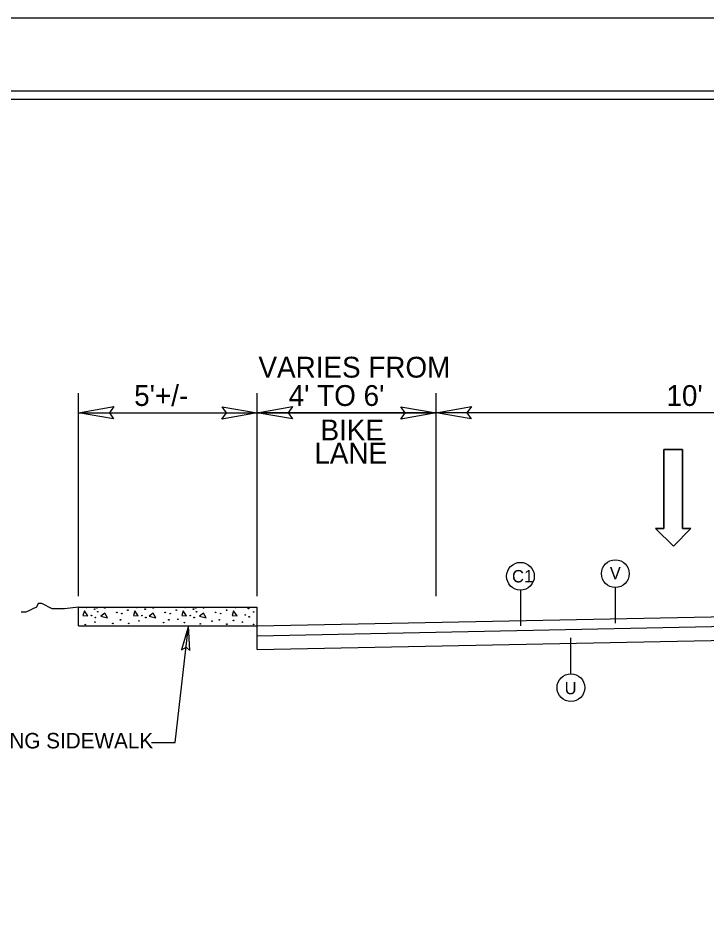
# Model space of a CAD drawing. Extents: x 1022283 to 1026986, y 174822 to 180471.
# Drawn here: x 1023136 to 1023665, y 179772 to 180471 of the extents above; entities that cross this region are included whole.
import ezdxf

# ---------------------------------------------------------------- set-up
doc = ezdxf.new("R2010")
doc.units = 0
for name, color, linetype in [('Default', 7, 'Continuous'), ('Old_Level_9', 7, 'Continuous'), ('Prop Dimension', 7, 'Continuous'), ('Prop Lane Arrow CELL', 7, 'Continuous'), ('Prop Terminator CELL', 7, 'Continuous'), ('Sheet Cutting Line CELL', 7, 'Continuous'), ('Sheet Plot Border Inside CELL', 7, 'Continuous'), ('Sheet Plot Border Outside CELL', 7, 'Continuous'), ('Sheet Typical CELL', 7, 'Continuous'), ('Typical Curb CELL', 7, 'Continuous'), ('Typical ID Circle CELL', 7, 'Continuous'), ('Typical Slope Point Local CELL', 7, 'Continuous'), ('Typical Text General CELL', 7, 'Continuous'), ('Typical Text ID Circle CELL', 7, 'Continuous')]:
    doc.layers.add(name, color=color, linetype=linetype)

# ---------------------------------------------------------------- blocks, each defined once
blk = doc.blocks.new('Lane Arrow Through')
at = {"layer": 'Prop Lane Arrow CELL'}
for p, q in [((-3.15, 1.6), (-3.15, 3.1)), ((-3.15, 3.1), (0, 0)), ((-17.15, 1.6), (-3.15, 1.6)), ((-17.15, -1.7), (-17.15, 1.6)), ((0, 0), (-3.15, -3.2)), ((-3.15, -1.7), (-17.15, -1.7)), ((-3.15, -3.2), (-3.15, -1.7))]:
    blk.add_line(p, q, dxfattribs=at)
blk = doc.blocks.new('Terminator')
at = {"layer": 'Prop Terminator CELL'}
blk.add_lwpolyline([(-9, 1.55), (0, 0), (-9.05, -1.6), (-7.9, 0)], close=True, dxfattribs=at)

msp = doc.modelspace()

# ---------------------------------------------------------------- linework, layer by layer
at = {"layer": 'Default'}
for p, q in [((1023182.77, 180027.22), (1023182.77, 180183.23)), ((1023182.77, 180027.22), (1023182.77, 180183.23)), ((1023182.77, 180027.22), (1023182.77, 180183.23)), ((1023320.14, 180027.22), (1023320.14, 180183.23)), ((1023320.14, 180027.22), (1023320.14, 180183.23)), ((1023457.52, 180027.22), (1023457.52, 180183.23)), ((1023182.77, 180168.23), (1023320.14, 180168.23)), ((1023182.77, 180168.23), (1023320.14, 180168.23)), ((1023827.85, 180168.23), (1023320.14, 180168.23)), ((1023827.85, 180168.23), (1023320.14, 180168.23)), ((1023320.14, 180168.23), (1023457.52, 180168.23))]:
    msp.add_line(p, q, dxfattribs=at)
at = {"layer": 'Old_Level_9'}
msp.add_lwpolyline([(1023639.83, 180065.79), (1023653.25, 180079.43), (1023646.76, 180079.43), (1023646.76, 180140.04), (1023632.47, 180140.04), (1023632.47, 180079.43), (1023625.97, 180079.43)], close=True, dxfattribs=at)
at = {"layer": 'Prop Dimension'}
for p, q in [((1023320.14, 180004.43), (1023827.85, 180014.58)), ((1023320.14, 180004.43), (1023827.85, 180014.58)), ((1023256.91, 179914.73), (1023267.27, 180004.43)), ((1023320.14, 179996.92), (1023827.85, 180007.08)), ((1023320.14, 179996.92), (1023827.85, 180007.08)), ((1023320.14, 179986.34), (1023827.85, 179996.5)), ((1023238.75, 179914.73), (1023256.91, 179914.73))]:
    msp.add_line(p, q, dxfattribs=at)
at = {"layer": 'Prop Terminator CELL'}
for points in [[(1023209.77, 180163.58), (1023182.77, 180168.23), (1023209.92, 180173.03), (1023206.47, 180168.23)], [(1023209.77, 180163.58), (1023182.77, 180168.23), (1023209.92, 180173.03), (1023206.47, 180168.23)], [(1023293.14, 180172.88), (1023320.14, 180168.23), (1023292.99, 180163.43), (1023296.44, 180168.23)], [(1023293.14, 180172.88), (1023320.14, 180168.23), (1023292.99, 180163.43), (1023296.44, 180168.23)], [(1023347.14, 180163.58), (1023320.14, 180168.23), (1023347.29, 180173.03), (1023343.84, 180168.23)], [(1023347.14, 180163.58), (1023320.14, 180168.23), (1023347.29, 180173.03), (1023343.84, 180168.23)], [(1023430.52, 180172.88), (1023457.52, 180168.23), (1023430.37, 180163.43), (1023433.82, 180168.23)], [(1023484.52, 180163.58), (1023457.52, 180168.23), (1023484.67, 180173.03), (1023481.22, 180168.23)]]:
    msp.add_lwpolyline(points, close=True, dxfattribs=at)
at = {"layer": 'Sheet Cutting Line CELL'}
msp.add_line((1026493.22, 180471.48), (1022283.22, 180471.48), dxfattribs=at)
at = {"layer": 'Sheet Plot Border Inside CELL'}
msp.add_lwpolyline([(1026481.97, 180415.35), (1022315.72, 180415.35), (1022315.72, 177777.6), (1026481.97, 177777.6)], close=True, dxfattribs=at)
at = {"layer": 'Sheet Plot Border Outside CELL'}
msp.add_lwpolyline([(1026493.22, 180471.48), (1022283.22, 180471.48), (1022283.22, 177721.48), (1026493.22, 177721.48)], close=True, dxfattribs=at)
at = {"layer": 'Sheet Typical CELL'}
msp.add_lwpolyline([(1026450.72, 180408.98), (1022700.72, 180408.98), (1022700.72, 177783.98), (1026450.72, 177783.98)], close=True, dxfattribs=at)
at = {"layer": 'Typical Curb CELL'}
for p, q in [((1023182.77, 180018.95), (1023320.14, 180018.95)), ((1023182.77, 180004.43), (1023182.77, 180018.95)), ((1023182.77, 180018.95), (1023320.14, 180018.95)), ((1023182.77, 180004.43), (1023182.77, 180018.95)), ((1023187.27, 180016.04), (1023186.2, 180012.52)), ((1023187.27, 180016.04), (1023186.2, 180012.52)), ((1023189.92, 180012.32), (1023187.27, 180016.04)), ((1023189.92, 180012.32), (1023187.27, 180016.04)), ((1023226, 180016.04), (1023224.93, 180012.52)), ((1023226, 180016.04), (1023224.93, 180012.52)), ((1023228.68, 180012.32), (1023226, 180016.04)), ((1023228.68, 180012.32), (1023226, 180016.04)), ((1023263.16, 180016.04), (1023262.1, 180012.52)), ((1023263.16, 180016.04), (1023262.1, 180012.52)), ((1023265.81, 180012.32), (1023263.16, 180016.04)), ((1023265.81, 180012.32), (1023263.16, 180016.04)), ((1023301.89, 180016.04), (1023300.82, 180012.52)), ((1023301.89, 180016.04), (1023300.82, 180012.52)), ((1023304.57, 180012.32), (1023301.89, 180016.04)), ((1023304.57, 180012.32), (1023301.89, 180016.04)), ((1023320.14, 179986.34), (1023320.14, 180018.95)), ((1023320.14, 180008.61), (1023320.14, 180018.95)), ((1023320.14, 179986.34), (1023320.14, 180018.95)), ((1023320.14, 180008.61), (1023320.14, 180018.95)), ((1023186.2, 180012.52), (1023189.92, 180012.32)), ((1023186.2, 180012.52), (1023189.92, 180012.32)), ((1023203, 180014.29), (1023199.8, 180011.97)), ((1023203, 180014.29), (1023199.8, 180011.97)), ((1023199.8, 180011.97), (1023204.94, 180010.74)), ((1023199.8, 180011.97), (1023204.94, 180010.74)), ((1023204.94, 180010.74), (1023203, 180014.29)), ((1023204.94, 180010.74), (1023203, 180014.29)), ((1023224.93, 180012.52), (1023228.68, 180012.32)), ((1023224.93, 180012.52), (1023228.68, 180012.32)), ((1023240.16, 180014.29), (1023236.97, 180011.97)), ((1023240.16, 180014.29), (1023236.97, 180011.97)), ((1023236.97, 180011.97), (1023242.1, 180010.74)), ((1023236.97, 180011.97), (1023242.1, 180010.74)), ((1023242.1, 180010.74), (1023240.16, 180014.29)), ((1023242.1, 180010.74), (1023240.16, 180014.29)), ((1023262.1, 180012.52), (1023265.81, 180012.32)), ((1023262.1, 180012.52), (1023265.81, 180012.32)), ((1023278.89, 180014.29), (1023275.69, 180011.97)), ((1023278.89, 180014.29), (1023275.69, 180011.97)), ((1023275.69, 180011.97), (1023280.83, 180010.74)), ((1023275.69, 180011.97), (1023280.83, 180010.74)), ((1023280.83, 180010.74), (1023278.89, 180014.29)), ((1023280.83, 180010.74), (1023278.89, 180014.29)), ((1023300.82, 180012.52), (1023304.57, 180012.32)), ((1023300.82, 180012.52), (1023304.57, 180012.32)), ((1023182.77, 180004.43), (1023320.14, 180004.43)), ((1023320.14, 179987.95), (1023320.14, 180005.93)), ((1023320.14, 179987.95), (1023320.14, 180005.93))]:
    msp.add_line(p, q, dxfattribs=at)
for centre in [(1023188.87, 180018.53), (1023188.87, 180018.53), (1023195.24, 180017.29), (1023195.24, 180017.29), (1023196.97, 180018.35), (1023196.97, 180018.35), (1023197.5, 180015.35), (1023197.5, 180015.35), (1023202.99, 180018.35), (1023202.99, 180018.35), (1023220.69, 180016.59), (1023220.69, 180016.59), (1023227.6, 180018.53), (1023227.6, 180018.53), (1023233.97, 180017.29), (1023233.97, 180017.29), (1023240.15, 180018.35), (1023240.15, 180018.35), (1023257.85, 180016.59), (1023257.85, 180016.59), (1023264.76, 180018.53), (1023264.76, 180018.53), (1023271.13, 180017.29), (1023271.13, 180017.29), (1023272.86, 180018.35), (1023272.86, 180018.35), (1023273.39, 180015.35), (1023273.39, 180015.35), (1023278.88, 180018.35), (1023278.88, 180018.35), (1023296.58, 180016.59), (1023296.58, 180016.59), (1023303.49, 180018.53), (1023303.49, 180018.53), (1023313.34, 180017.83), (1023313.34, 180017.83), (1023317.28, 180015.15), (1023317.28, 180015.15), (1023192.75, 180012.34), (1023192.75, 180012.34), (1023195.74, 180010.92), (1023195.74, 180010.92), (1023212.19, 180014.81), (1023212.19, 180014.81), (1023215.03, 180009.15), (1023215.03, 180009.15), (1023216.09, 180013.93), (1023216.09, 180013.93), (1023229.24, 180008.3), (1023229.24, 180008.3), (1023231.49, 180012.34), (1023231.49, 180012.34), (1023234.47, 180010.92), (1023234.47, 180010.92), (1023249.35, 180014.81), (1023249.35, 180014.81), (1023252.19, 180009.15), (1023252.19, 180009.15), (1023253.24, 180013.93), (1023253.24, 180013.93), (1023259.15, 180009.52), (1023259.15, 180009.52), (1023268.64, 180012.34), (1023268.64, 180012.34), (1023271.63, 180010.92), (1023271.63, 180010.92), (1023285.31, 180008.1), (1023285.31, 180008.1), (1023288.08, 180014.81), (1023288.08, 180014.81), (1023290.92, 180009.15), (1023290.92, 180009.15), (1023291.98, 180013.93), (1023291.98, 180013.93), (1023301.84, 180008.68), (1023301.84, 180008.68), (1023310.86, 180012.87), (1023310.86, 180012.87), (1023313.84, 180011.45), (1023313.84, 180011.45), (1023187.97, 180005.45), (1023187.97, 180005.45), (1023195.39, 180007.39), (1023195.39, 180007.39), (1023209.09, 180006.42), (1023209.09, 180006.42), (1023221.36, 180006.42), (1023221.36, 180006.42), (1023248.17, 180007), (1023248.17, 180007), (1023264.12, 180007), (1023264.12, 180007), (1023276.33, 180006.03), (1023276.33, 180006.03), (1023296.74, 180005.78), (1023296.74, 180005.78), (1023308.69, 180007.39), (1023308.69, 180007.39), (1023317.28, 180005.65), (1023317.28, 180005.65)]:
    msp.add_circle(centre, 0.249, dxfattribs=at)
at = {"layer": 'Typical ID Circle CELL'}
for p, q in [((1023522.32, 180031.97), (1023522.32, 180004.44)), ((1023595.21, 180033.98), (1023595.21, 180006.45)), ((1023561.08, 179967.65), (1023561.08, 179995.18))]:
    msp.add_line(p, q, dxfattribs=at)
for centre in [(1023522.32, 180042.62), (1023595.21, 180044.62), (1023561.08, 179957)]:
    msp.add_circle(centre, 10.65, dxfattribs=at)
at = {"layer": 'Typical Slope Point Local CELL'}
msp.add_lwpolyline([(1023182.77, 180018.95), (1023171.99, 180017.61), (1023169.3, 180017.61), (1023165.26, 180017.61), (1023162.56, 180017.61), (1023159.87, 180018.95), (1023157.18, 180020.3), (1023154.49, 180021.66), (1023151.79, 180021.66), (1023150.44, 180018.95), (1023147.75, 180017.61), (1023145.06, 180016.26), (1023142.36, 180014.92), (1023139.67, 180014.92), (1023138.61, 180014.92)], dxfattribs=at)
msp.add_lwpolyline([(1023182.77, 180018.95), (1023171.99, 180017.61), (1023169.3, 180017.61), (1023165.26, 180017.61), (1023162.56, 180017.61), (1023159.87, 180018.95), (1023157.18, 180020.3), (1023154.49, 180021.66), (1023151.79, 180021.66), (1023150.44, 180018.95), (1023147.75, 180017.61), (1023145.06, 180016.26), (1023142.36, 180014.92), (1023139.67, 180014.92), (1023138.61, 180014.92)], dxfattribs=at)

# ---------------------------------------------------------------- block references
at = {"layer": 'Prop Dimension', "xscale": 2.0767499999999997, "yscale": -2.076749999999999, "rotation": 83.4116733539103}
msp.add_blockref('Terminator', (1023267.27, 180004.43), dxfattribs=at)
at = {"layer": 'Prop Lane Arrow CELL', "xscale": 4.329849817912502, "yscale": 4.3298498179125, "rotation": -89.99999999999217}
msp.add_blockref('Lane Arrow Through', (1023639.83, 180065.79), dxfattribs=at)

# ---------------------------------------------------------------- texts
at = {"layer": 'Prop Dimension'}
for s, p in [('VARIES FROM', (1023321.02, 180195.28)), ("5'+/-", (1023225.52, 180173.5)), ("4' TO 6'", (1023344.23, 180173.5)), ("10'", (1023634.51, 180173.5)), ('BIKE', (1023368.72, 180147.03)), ('LANE', (1023363.97, 180129.19))]:
    msp.add_text(s, height=16, dxfattribs=at).set_placement(p)
at = {"layer": 'Typical Text General CELL'}
msp.add_text('EXISTING SIDEWALK', height=11.8979, dxfattribs=at).set_placement((1023079.24, 179910.3))
at = {"layer": 'Typical Text ID Circle CELL'}
for s, height, p in [('C1', 9.534, (1023515.85, 180037.88)), ('V', 9.53, (1023590.97, 180040.32)), ('U', 9.53, (1023556.26, 179951.94))]:
    msp.add_text(s, height=height, dxfattribs=at).set_placement(p)

doc.saveas('drawing.dxf')
